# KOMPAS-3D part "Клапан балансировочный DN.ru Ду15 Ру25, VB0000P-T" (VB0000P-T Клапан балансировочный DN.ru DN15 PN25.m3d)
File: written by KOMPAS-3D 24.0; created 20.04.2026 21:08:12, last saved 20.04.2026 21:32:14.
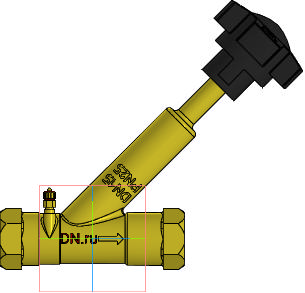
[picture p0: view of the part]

Document properties: Автор: DN.ru; Полное имя файла: VB0000P-T DN15 PN25 Клапан балансировочный DN.ru.cdw

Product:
- Part/product: Клапан балансировочный DN.ru Ду15 Ру25  | designation VB0000P-T
    Масса: 0.49
    Раздел спецификации: Прочие изделия
    Форматы листов документа: A4
    Примечание: D080-01175

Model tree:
1. Операция без истории:1

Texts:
  VB0000P-T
